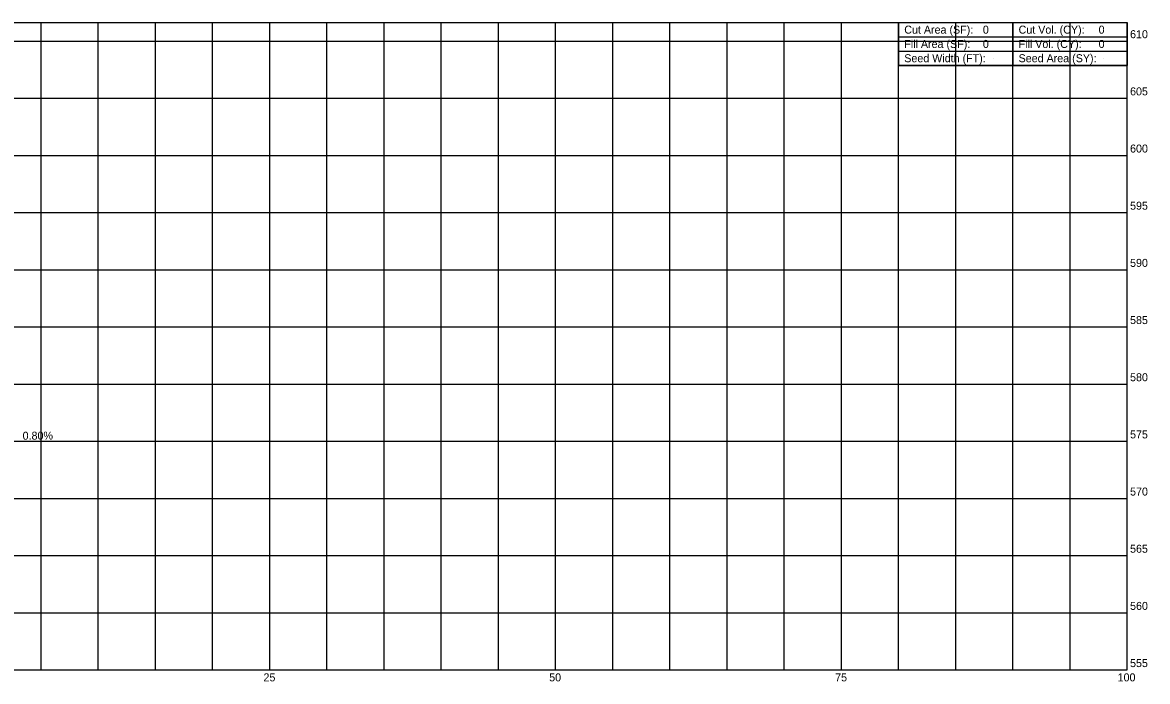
# Model space of a CAD drawing. Extents: x -102 to 102, y 554 to 612.
# Drawn here: x 3.4 to 101.8, y 554 to 611.6 of the extents above; entities that cross this region are included whole.
import ezdxf

# ---------------------------------------------------------------- set-up
doc = ezdxf.new("R2010")
doc.units = 0
for name, color, linetype in [('Default', 7, 'Continuous'), ('SH_Data', 7, 'Continuous'), ('SH_Major_Grid_Line', 7, 'Continuous'), ('SH_Masking', 7, 'Continuous'), ('SH_Text', 7, 'Continuous')]:
    doc.layers.add(name, color=color, linetype=linetype)

msp = doc.modelspace()

# ---------------------------------------------------------------- linework, layer by layer
at = {"layer": 'Default'}
msp.add_circle((100, 611.623), 0.000417, dxfattribs=at)
msp.add_circle((100, 611.623), 0.000417, dxfattribs=at)
msp.add_circle((100, 611.623), 0.000417, dxfattribs=at)
msp.add_circle((100, 611.623), 0.000417, dxfattribs=at)
msp.add_circle((100, 611.623), 0.000417, dxfattribs=at)
msp.add_circle((100, 611.623), 0.000417, dxfattribs=at)
msp.add_circle((100, 611.623), 0.000417, dxfattribs=at)
msp.add_circle((100, 611.623), 0.000417, dxfattribs=at)
msp.add_circle((100, 611.623), 0.000417, dxfattribs=at)
msp.add_circle((100, 611.623), 0.000417, dxfattribs=at)
msp.add_circle((100, 611.623), 0.000417, dxfattribs=at)
msp.add_circle((100, 611.623), 0.000417, dxfattribs=at)
at = {"layer": 'SH_Data'}
for p, q in [((80, 611.623), (100, 611.623)), ((80, 611.623), (80, 609.123)), ((90, 611.623), (90, 607.873)), ((100, 611.623), (100, 609.123)), ((80, 610.373), (100, 610.373)), ((80, 609.123), (100, 609.123)), ((88.298, 608.498), (88.298, 608.498)), ((97.946, 608.498), (97.946, 608.498))]:
    msp.add_line(p, q, dxfattribs=at)
msp.add_lwpolyline([(80, 609.123), (80, 607.873), (100, 607.873), (100, 609.123)], dxfattribs=at)
at = {"layer": 'SH_Major_Grid_Line'}
for p, q in [((-100, 611.623), (100, 611.623)), ((5, 555), (5, 611.623)), ((10, 555), (10, 611.623)), ((15, 555), (15, 611.623)), ((20, 555), (20, 611.623)), ((25, 555), (25, 611.623)), ((30, 555), (30, 611.623)), ((35, 555), (35, 611.623)), ((40, 555), (40, 611.623)), ((45, 555), (45, 611.623)), ((50, 555), (50, 611.623)), ((55, 555), (55, 611.623)), ((60, 555), (60, 611.623)), ((65, 555), (65, 611.623)), ((70, 555), (70, 611.623)), ((75, 555), (75, 611.623)), ((80, 555), (80, 611.623)), ((85, 555), (85, 611.623)), ((90, 555), (90, 611.623)), ((95, 555), (95, 611.623)), ((100, 555), (100, 611.623)), ((-100, 610), (100, 610)), ((-100, 605), (100, 605)), ((-100, 600), (100, 600)), ((-100, 595), (100, 595)), ((-100, 590), (100, 590)), ((-100, 585), (100, 585)), ((-100, 580), (100, 580)), ((-100, 575), (100, 575)), ((-100, 570), (100, 570)), ((-100, 565), (100, 565)), ((-100, 560), (100, 560)), ((-100, 555), (100, 555))]:
    msp.add_line(p, q, dxfattribs=at)
at = {"layer": 'SH_Masking'}
msp.add_lwpolyline([(80, 611.623), (100, 611.623), (100, 607.873), (80, 607.873)], close=True, dxfattribs=at)

# ---------------------------------------------------------------- texts
at = {"layer": 'SH_Text'}
for s, p in [('Cut Area (SF):', (80.5, 610.648)), ('0', (87.375, 610.648)), ('Cut Vol. (CY):', (90.5, 610.648)), ('0', (97.5, 610.648)), ('Fill Area (SF):', (80.5, 609.398)), ('0', (87.375, 609.398)), ('Fill Vol. (CY):', (90.5, 609.398)), ('0', (97.5, 609.398)), ('610', (100.25, 610.25)), ('Seed Width (FT):', (80.5, 608.148)), ('Seed Area (SY):', (90.5, 608.148)), ('605', (100.25, 605.25)), ('600', (100.25, 600.25)), ('595', (100.25, 595.25)), ('590', (100.25, 590.25)), ('585', (100.25, 585.25)), ('580', (100.25, 580.25)), ('575', (100.25, 575.25)), ('570', (100.25, 570.25)), ('565', (100.25, 565.25)), ('560', (100.25, 560.25)), ('555', (100.25, 555.25)), ('25', (24.453, 554)), ('50', (49.443, 554)), ('75', (74.453, 554)), ('100', (99.163, 554))]:
    msp.add_text(s, height=0.7, dxfattribs=at).set_placement(p)
msp.add_text('0.80%', height=0.7, rotation=0.45836, dxfattribs=at).set_placement((3.388, 575.132))

doc.saveas('drawing.dxf')
